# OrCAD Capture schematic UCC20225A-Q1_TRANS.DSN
size E; title: UCC20225A-Q1 Isolated Dual-Channel Gate Driver with Single; rev: 1.0; note: Input in LGA for Automotive 48-V Systems
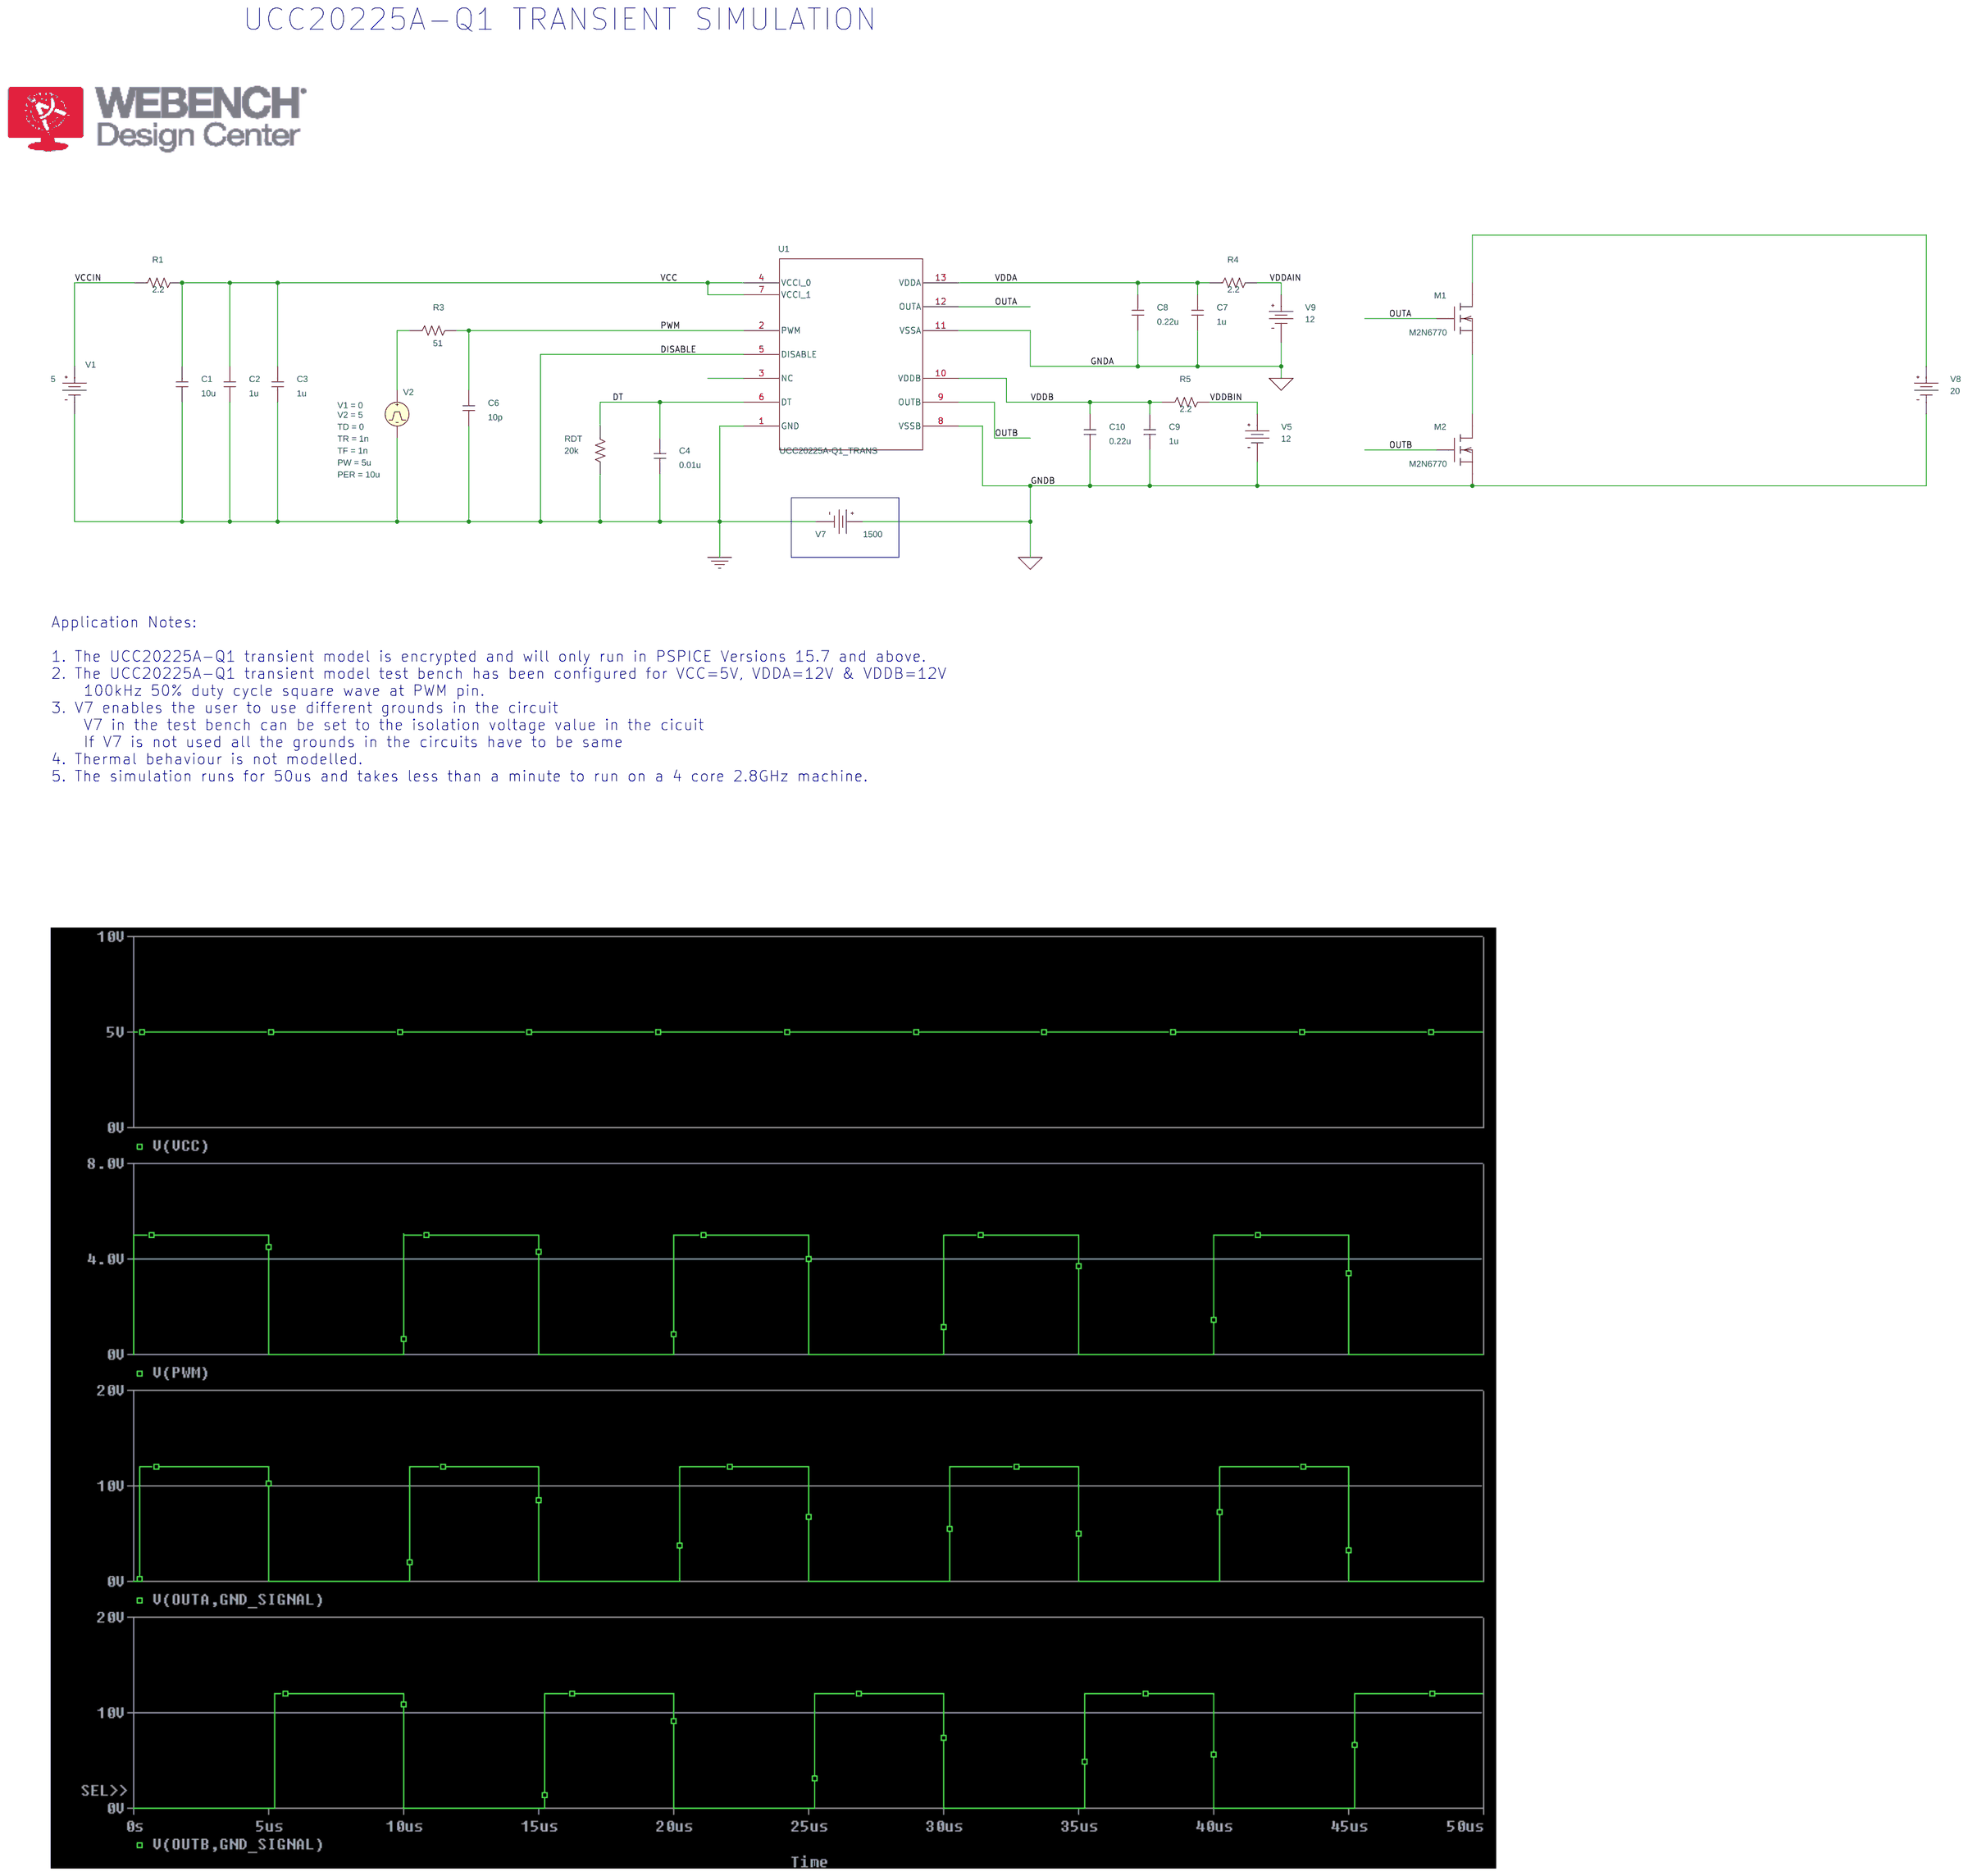
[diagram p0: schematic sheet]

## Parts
C1  10u  [RAD/CK05]
C2  1u  [RAD/CK05]
C3  1u  [RAD/CK05]
C4  0.01u  [RAD/CK05]
C6  10p  [RAD/CK05]
C7  1u  [RAD/CK05]
C8  0.22u  [RAD/CK05]
C9  1u  [RAD/CK05]
C10  0.22u  [RAD/CK05]
M1  M2N6770  [TO204]
M2  M2N6770  [TO204]
R1  2.2  [AX/RC05]
R3  51  [AX/RC05]
R4  2.2  [AX/RC05]
R5  2.2  [AX/RC05]
RDT  20k  [AX/RC05]
U1  UCC20225A-Q1_TRANS  [NPL0013A]
V1  VDC
V2  VPULSE
V5  VDC
V7  VDC
V8  VDC
V9  VDC

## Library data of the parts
C1-C4 C6-C10 = C
M1 M2 = 2N6770
R1 R3-R5 RDT = R
U1 = UCC20225A-Q1_TRANS
V1 = VDC: DC: 5
V2 = VPULSE: PER: 10u; PW: 5u; TD: 0; TF: 1n; TR: 1n; V1: 0; V2: 5
V5 V9 = VDC: DC: 12
V7 = VDC: DC: 1500
V8 = VDC: DC: 20

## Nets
GND_SIGNAL: C7.2 C8.2 C9.2 C10.2 M2.2(s) U1.8(VSSB) U1.11(VSSA) V5.1(-) V7.0(+) V8.1(-) V9.1(-)
VCC: C1.1 C2.1 C3.1 R1.2 U1.4(VCCI_0) U1.7(VCCI_1)
VCCIN: R1.1 V1.0(+)
VDDA: C7.1 C8.1 R4.1 U1.13(VDDA)
VDDAIN: R4.2 V9.0(+)
VDDB: C9.1 C10.1 R5.1 U1.10(VDDB)
VDDBIN: R5.2 V5.0(+)
0: C1.2 C2.2 C3.2 C4.2 C6.2 RDT.2 U1.1(GND) U1.5(DISABLE) V1.1(-) V2.2(-) V7.1(-)
DT: C4.1 RDT.1 U1.6(DT)
OUTA: M1.1(g) U1.12(OUTA)
OUTB: M2.1(g) U1.9(OUTB)
PWM: C6.1 R3.2 U1.2(PWM)
N16773307: R3.1 V2.1(+)
N16784602: M1.3(d) V8.0(+)
N16784614: M1.2(s) M2.3(d)

Not connected (* = marked no-connect by the designer): U1 3(NC)

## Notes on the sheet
- UCC20225A-Q1 TRANSIENT SIMULATION
- Application Notes:
  1. The UCC20225A-Q1 transient model is encrypted and will only run in PSPICE Versions 15.7 and above.
  2. The UCC20225A-Q1 transient model test bench has been configured for VCC=5V, VDDA=12V & VDDB=12V
      100kHz 50% duty cycle square wave at PWM pin.
  3. V7 enables the user to use different grounds in the circuit
      V7 in the test bench can be set to the isolation voltage value in the cicuit
      If V7 is not used all the grounds in the circuits have to be same
  4. Thermal behaviour is not modelled.
  5. The simulation runs for 50us and takes less than a minute to run on a 4 core 2.8GHz machine.
